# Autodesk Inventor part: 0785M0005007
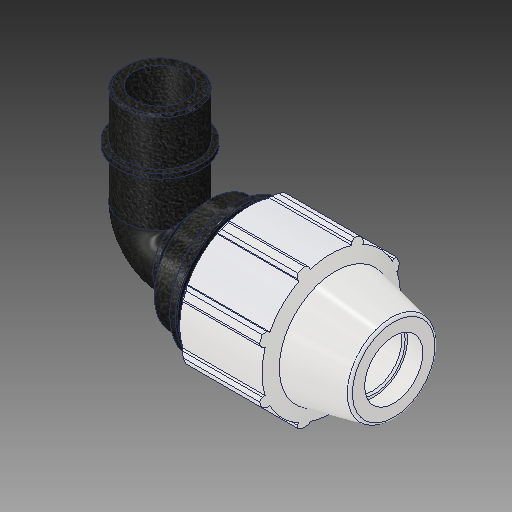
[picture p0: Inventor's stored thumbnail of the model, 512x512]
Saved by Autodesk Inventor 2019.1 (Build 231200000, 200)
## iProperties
Created: 2017-02
Part Number: 0785M0005007
Material: PVC-Piping
Description: PLASSON 90° ELBOW MALE ADAPTOR 1/2''-3/4''M
Document SubType Name: Modeling
Designer: KIM
Mass: 92.6774 g
Surface Area: 199.44 cm^2
Volume: 66.1981 cm^3
Density: 1.4 g/cm^3
Appearance: PTFE
Author: KIM
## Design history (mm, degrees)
derived "0785M0.ipt"
feature "Solid1::0785M0.ipt"
tag "TaggingFeature1"
body "Solid1"
other parameters: "d2" = 21.2, "d4" = 7.09083, "d5" = 21.2725, "d7" = 54.102, "d9" = 12.15571, "d11" = 2.83633, "d13" = 120 deg, "d14" = 31.8, "d15" = 12 deg, "d16" = 47.06874, "d18" = 1.06, "d19" = 35 deg, "d20" = 17.5 deg, "d21" = 50.31486, "d23" = 0, "d25" = 360 deg, "d27" = 1.08204, "d33" = 0.424, "d42" = 31.4833, "d43" = 1.62306, "d46" = 0.636, "d51" = 85.09, "d68" = 2.83633, "d72" = 46.99, "d73" = 26.441, "d74" = 17.018, "d75" = 30.40715, "d76" = 18.5087, "d77" = 18.7198, "d79" = 10.5764, "d80" = 0.79323, "d83" = 0, "d84" = 0, "d91" = 40.5765, "d93" = 57.912, "d94" = 26.441, "d95" = 18.5087, "d96" = 8.509, "d97" = 50 deg, "d_" = 21.2, "E_" = 54.102, "A_" = 85.09, "l_" = 57.912, "l_2" = 17.018, "A_1" = 46.99, "G_" = 26.441
